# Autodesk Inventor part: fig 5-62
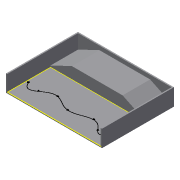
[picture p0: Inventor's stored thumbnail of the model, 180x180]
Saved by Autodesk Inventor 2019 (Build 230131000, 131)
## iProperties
Created: 2004-05
Part Number: fig 5-62
Document SubType Name: Modeling
Designer: CADCIM Technologies
Manufacturer: Standard
Standards Organization: Custom
Density: 1 g/cm^3
Material: Generic
Appearance: Default
Author: CADCIM Technologies
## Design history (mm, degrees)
sketch "Sketch1"
  geometry: L1 (-40, -30)-(40, -30); L2 (40, -30)-(40, 30); L3 (40, 30)-(-40, 30); L4 (-40, 30)-(-40, -30); 1 further point
  constraints: 8 end point, 2 parallel, 1 horizontal, 1 perpendicular, 1 other
  dimensions: "d0" = 80 distance of L1.start L1.end; "d1" = 60 distance of L3.end L1.start; "d2" = 30 distance from line of point (0, 0) L1; "d3" = 40 distance from line of point (0, 0) L4
extrude "Extrusion1" new body sketch "Sketch1" distance "d4" = 14; taper "d5" = 0 deg
shell "Shell1" dims "d6" = 1
workplane "Work Plane1"
sketch "Sketch2"
  geometry: L1 (78, -13)-(78, -11.813); L2 (0, -11.813)-(0, -13); L3 (0, -13)-(78, -13); L4 (0, -11.813)-(17.826, -3.295); L5 (17.826, -3.295)-(60.174, -3.295); L6 (60.174, -3.295)-(78, -11.813); L7 (79, -13.795)-(78, -13.795); L8 (78, 0)-(78, -13) reference; L9 (0, -13)-(0, 0) reference; L10 (78, -13)-(0, -13) reference
  constraints: 14 end point, 3 collinear, 2 equal length, 2 vertical, 1 horizontal alignment, 1 parallel, 1 point on line
extrude "Extrusion2" join sketch "Sketch2" stored distance "d8" = 14; taper "d9" = 0 deg
workplane "Work Plane2"
sketch "Sketch4"
  geometry: L1 (78, 36)-(0, 36) reference; L2 (0, 36)-(0, 0) reference; L3 (78, 0)-(0, 0) reference; L4 (78, 0)-(78, 36) reference; 7 further points
  constraints: 7 other
body "Solid1"
other parameters: "d7" = 23, "d18" = 4
